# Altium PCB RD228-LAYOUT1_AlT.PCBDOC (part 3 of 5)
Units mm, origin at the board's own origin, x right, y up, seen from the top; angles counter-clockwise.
Board outline 130 x 73 mm, 4 copper layers (TOP, Mid-Layer 1, Mid-Layer 2, BOTTOM), stack 0.711 mm thick; 225 components, 171 nets, 818 pads, 538 vias.
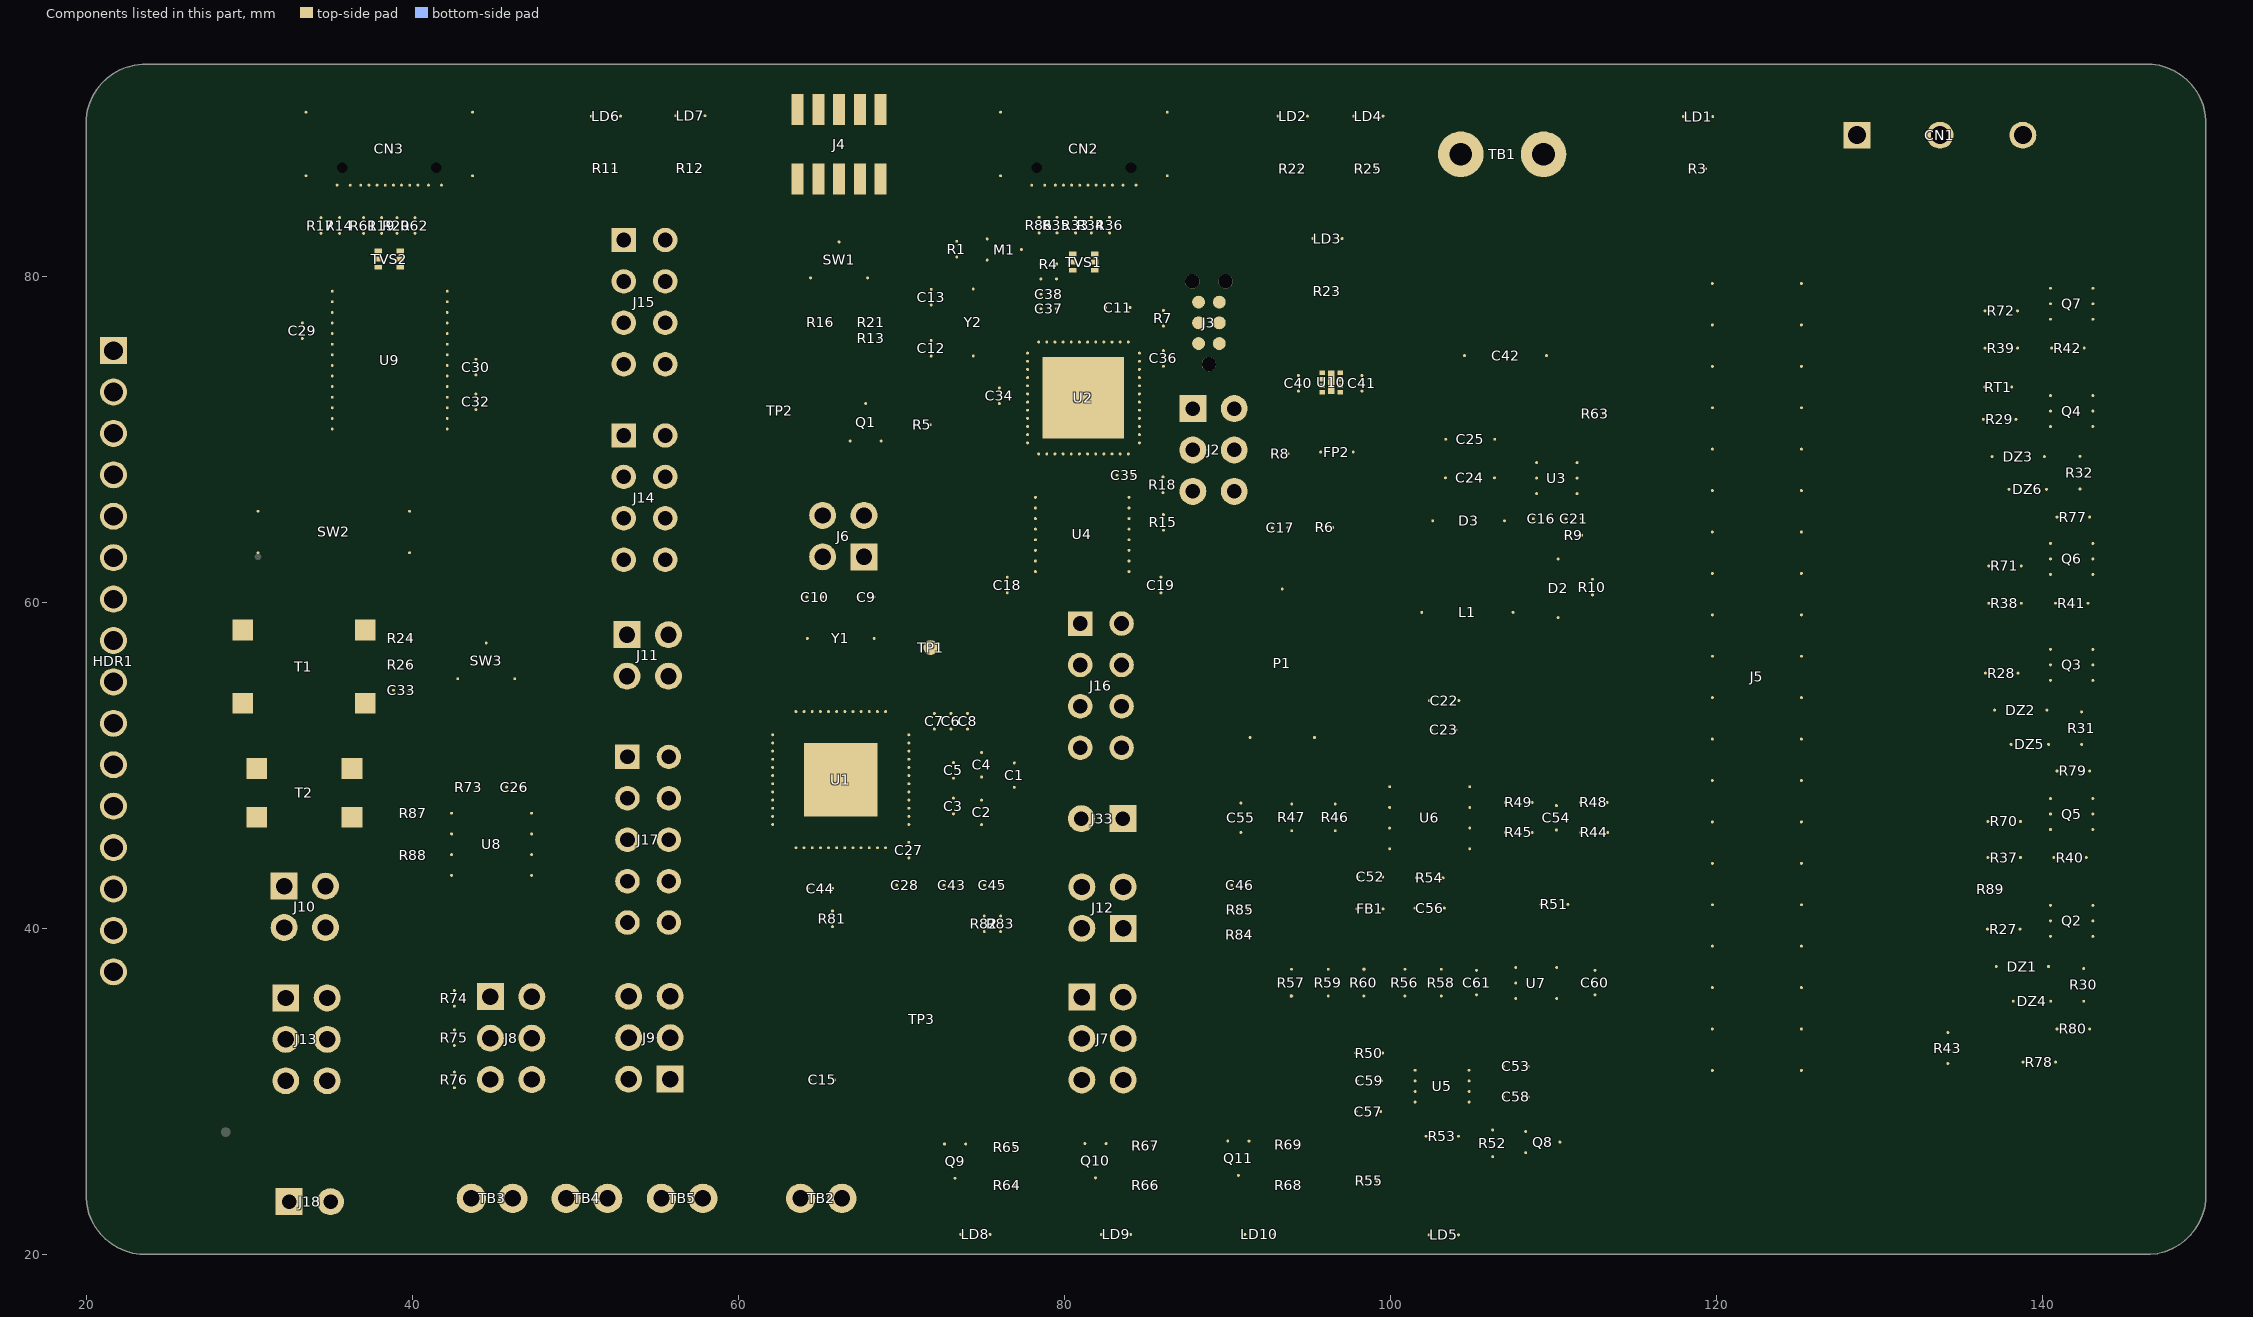
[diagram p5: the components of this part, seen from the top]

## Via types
v1: diameter 0.406, hole 0.203, TOP to BOTTOM, tented both sides, 533 vias
v2: diameter 6, hole 4.2, TOP to BOTTOM, 4 vias
v3: diameter 1.651, hole 1, TOP to BOTTOM, 1 vias

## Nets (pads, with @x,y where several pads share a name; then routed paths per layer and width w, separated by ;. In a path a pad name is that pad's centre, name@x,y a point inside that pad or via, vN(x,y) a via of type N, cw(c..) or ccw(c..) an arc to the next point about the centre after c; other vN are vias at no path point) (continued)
copper on no net:
  other v2: 24.24,27.502 145.739,27.502 24.24,85.502 145.74,85.502

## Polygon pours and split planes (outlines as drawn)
GND on TOP "TOP36" (solid, pour order 54): 31 vertices, not listed, extent 86.069,72.96 88.601,75.77
GND on TOP "TOP35" (solid, pour order 53): 49 vertices, not listed, extent 77.876,81.153 80.589,82.648
GND on TOP "TOP34" (solid, pour order 52): 45 vertices, not listed, extent 109.822,66.46 113.288,69.427
GND on TOP "TOP33" (solid, pour order 51): 25 vertices, not listed, extent 39.176,71.553 42.147,74.232
GND on TOP "TOP32" (solid, pour order 50): 398 vertices, not listed, extent 20.389,20.391 122.57,92.614
GND on TOP "TOP16" (solid, pour order 34): 117.334,30.702 117.057,30.979 117.057,36.389 117.619,36.951 121.223,36.951 121.223,30.702
GND on TOP "TOP11" (solid, pour order 29): 102.948,64.124 101.555,64.124 101.391,64.289 101.391,65.686 101.56,65.856 102.947,65.856
GND on TOP "TOP9" (solid, pour order 27): 103.748,69.128 102.356,69.128 102.191,69.292 102.191,70.69 102.36,70.86 103.748,70.86
GND on TOP "TOP10" (solid, pour order 28): 103.724,66.761 102.332,66.761 102.167,66.926 102.167,68.324 102.336,68.494 103.724,68.494
GND on TOP "TOP14" (solid, pour order 32): 102.527,74.499 102.349,74.677 102.349,75.541 102.501,75.693 103.848,75.693 103.848,74.499
GND on TOP "TOP5" (solid, pour order 23): 76.493,49.854 76.493,51.048 76.544,51.099 77.281,51.099 77.357,51.022 77.357,49.854
GND on TOP "TOP6" (solid, pour order 24): 74.487,50.489 74.487,51.683 74.538,51.734 75.274,51.734 75.35,51.657 75.35,50.489
GND on TOP "TOP7" (solid, pour order 25): 74.563,45.409 74.487,45.485 74.487,46.654 75.35,46.654 75.35,45.46 75.3,45.409
VCC-5V on TOP "TOP29" (solid, pour order 47): 103.428,51.367 103.29,51.505 103.29,54.947 102.973,55.264 101.462,55.264 101.081,55.645 101.081,62.859 101.284,63.062 103.824,63.062 103.976,62.91 103.976,57.195 105.627,55.544 105.627,51.505 105.49,51.367
GND on TOP "TOP13" (solid, pour order 31): 101.484,51.734 101.391,51.827 101.391,52.475 101.512,52.597 102.819,52.597 102.819,51.734
GND on TOP "TOP12" (solid, pour order 30): 101.385,53.359 101.208,53.537 101.208,54.401 101.36,54.553 102.706,54.553 102.706,53.359
VCC-3.3V on TOP "TOP31" (solid, pour order 49): 93.588,73.298 93.486,73.4 93.486,74.111 93.588,74.213 95.993,74.213 95.993,73.552 94.172,73.552 93.918,73.298
VCC-5V on TOP "TOP30" (solid, pour order 48): 94.707,68.599 94.529,68.777 94.529,69.641 94.681,69.793 96.028,69.793 96.028,68.599
NetC16_1 on TOP "TOP24" (solid, pour order 42): 106.084,55.696 105.576,56.204 105.576,65.499 106.441,66.364 107.405,66.364 108.015,66.974 109.64,66.974 109.844,66.77 109.844,66.224 109.234,65.615 109.234,56.153 108.777,55.696
VBAT on TOP "TOP18" (solid, pour order 36): 20 vertices, not listed, extent 104.916,66.796 121.325,90.519
VBAT on TOP "TOP17" (solid, pour order 35): 72.689,47.797 72.258,48.228 69.661,48.228 69.661,49.016 72.328,49.016 72.709,49.397 77.916,49.397 78.475,48.838 78.475,48.317 77.967,47.809 77.967,47.797
GND on TOP "TOP15" (solid, pour order 33): 96.483,72.231 96.178,72.536 96.178,72.968 96.204,72.993 97.906,72.993 98.007,73.095 98.49,73.095 98.49,72.509 98.195,72.231
GND on TOP "TOP8" (solid, pour order 26): 110.73,67.126 110.617,67.239 110.617,67.974 110.76,68.117 112.536,68.117 112.638,68.015 112.638,67.253 112.511,67.126
NetC41_2 on TOP "TOP1" (solid, pour order 19): 98.795,73.552 96.737,73.552 96.737,74.213 98.693,74.213 98.795,74.111
LS_SOURCE on TOP "TOP28" (solid, pour order 46): 132.094,33.801 132.094,35.274 132.272,35.452 135.904,35.452 136.26,35.097 136.26,33.801
LS_SOURCE on TOP "TOP27" (solid, pour order 45): 142.102,43.53 141.85,43.781 141.85,46.298 142.075,46.527 144.921,46.527 145.15,46.298 145.15,43.758 144.921,43.53
LS_SOURCE on TOP "TOP26" (solid, pour order 44): 142.102,59.125 141.85,59.377 141.85,61.894 142.1,62.148 144.896,62.148 145.15,61.894 145.15,59.354 144.921,59.125
LS_SOURCE on TOP "TOP25" (solid, pour order 43): 142.102,74.771 141.85,75.023 141.85,77.54 142.1,77.794 144.896,77.794 145.15,77.54 145.15,75 144.921,74.771
RSL_INT on TOP "TOP23" (solid, pour order 41): 125.363,28.442 123.61,30.194 123.61,36.848 123.764,37.002 126.506,37.002 126.76,36.748 126.76,31.49 126.735,31.439 127.166,31.007 131.611,31.007 132.119,31.515 132.145,31.49 136.26,31.49 136.26,29.763 134.939,28.442
VBAT_INT on TOP "TOP22" (solid, pour order 40): 139.968,40.052 139.765,40.255 139.765,42.795 140.095,43.126 143.575,43.126 143.88,42.821 143.88,40.281 143.651,40.052
VBAT_INT on TOP "TOP21" (solid, pour order 39): 139.968,55.75 139.765,55.953 139.765,58.493 140.095,58.823 143.575,58.823 143.88,58.519 143.88,55.979 143.651,55.75
VBAT_INT on TOP "TOP20" (solid, pour order 38): 139.968,71.317 139.765,71.52 139.765,74.06 140.095,74.39 143.575,74.39 143.88,74.086 143.88,71.546 143.651,71.317
VBAT_INT on TOP "TOP19" (solid, pour order 37): 122.401,73.873 122.036,74.238 122.036,79.851 122.34,80.156 126.608,80.156 126.785,79.978 126.785,74.06 126.598,73.873
PHASE_W on TOP "TOP4" (solid, pour order 22): 18 vertices, not listed, extent 138.241,69.615 148.071,79.953
PHASE_V on TOP "TOP3" (solid, pour order 21): 20 vertices, not listed, extent 138.241,53.969 148.071,64.307
PHASE_U on TOP "TOP2" (solid, pour order 20): 20 vertices, not listed, extent 138.241,38.323 148.071,48.661
GND on Mid-Layer 1 "MID143" (solid, pour order 18): 20 vertices, not listed, extent 77.55,58.217 100.714,60.897
GND on Mid-Layer 1 "MID142" (solid, pour order 17): 90.047,44.628 89.995,44.755 90.491,45.251 96.191,45.251 96.259,45.124 96.251,45.113 96.222,44.964 96.251,44.815 96.292,44.755 96.224,44.628
GND on Mid-Layer 1 "MID141" (solid, pour order 16): 32 vertices, not listed, extent 64.566,42.622 78.867,46.098
GND on Mid-Layer 1 "MID140" (solid, pour order 15): 90 vertices, not listed, extent 20.312,20.313 122.57,92.692
PHASE_W on Mid-Layer 1 "MID139" (solid, pour order 14): 146.47,72.46 146.216,72.714 146.216,76.321 137.403,85.135 137.403,89.503 137.758,89.859 139.689,89.859 140.12,89.427 140.12,86.137 148.452,77.806 148.452,72.714 148.198,72.46
PHASE_V on Mid-Layer 1 "MID138" (solid, pour order 13): 146.47,56.814 146.216,57.068 146.216,60.675 132.221,74.67 132.221,89.503 132.577,89.859 134.837,89.859 135.193,89.503 135.193,75.419 148.452,62.16 148.452,57.068 148.198,56.814
PHASE_U on Mid-Layer 1 "MID137" (solid, pour order 12): 146.47,41.168 146.216,41.422 146.216,45.029 127.192,64.054 127.192,89.554 127.497,89.859 129.757,89.859 130.113,89.503 130.113,64.853 148.452,46.514 148.452,41.422 148.198,41.168
GND on Mid-Layer 2 "MID247" (solid, pour order 11): 90 vertices, not listed, extent 20.312,20.313 122.57,92.692
PHASE_W on Mid-Layer 2 "MID246" (solid, pour order 10): 146.47,72.46 146.216,72.714 146.216,76.321 137.403,85.135 137.403,89.503 137.758,89.859 139.689,89.859 140.12,89.427 140.12,86.137 148.452,77.806 148.452,72.714 148.198,72.46
PHASE_V on Mid-Layer 2 "MID245" (solid, pour order 9): 146.47,56.814 146.216,57.068 146.216,60.675 132.221,74.67 132.221,89.503 132.577,89.859 134.837,89.859 135.193,89.503 135.193,75.419 148.452,62.16 148.452,57.068 148.198,56.814
PHASE_U on Mid-Layer 2 "MID244" (solid, pour order 8): 146.47,41.168 146.216,41.422 146.216,45.029 127.192,64.054 127.192,89.554 127.497,89.859 129.757,89.859 130.113,89.503 130.113,64.853 148.452,46.514 148.452,41.422 148.198,41.168
VCC-3.3V on BOTTOM "BOTTOM53" (solid, pour order 7): 74 vertices, not listed, extent 75.071,66.745 94.35,81.426
GND on BOTTOM "BOTTOM52" (solid, pour order 6): 50 vertices, not listed, extent 20.312,20.313 122.57,92.692
VBAT on BOTTOM "BOTTOM48" (solid, pour order 2): 77.484,47.822 77.23,48.076 77.23,48.965 77.484,49.219 78.221,49.219 78.475,48.965 78.475,48.076 78.221,47.822
LS_SOURCE on BOTTOM "BOTTOM51" (solid, pour order 5): 132.653,33.725 132.196,34.182 132.196,35.503 132.602,35.909 142.813,35.909 143.981,37.078 143.981,43.758 146.328,43.768 146.328,36.107 143.946,33.725
LS_SOURCE on BOTTOM "BOTTOM50" (solid, pour order 4): 144.21,43.529 144.007,43.733 144.007,77.261 144.159,77.413 146.166,77.413 146.328,77.25 146.328,43.768 146.089,43.529
VBAT_INT on BOTTOM "BOTTOM49" (solid, pour order 3): 140.247,41.726 139.765,42.209 139.765,73.247 138.088,74.924 122.417,74.924 122.137,75.203 122.137,79.623 122.366,79.851 138.977,79.851 143.803,75.025 143.804,42.234 143.295,41.726
no net on Top Overlay "TOPOVERLAY983" (solid, pour order 0): 216 vertices, not listed, extent 144.999,39.951 145.644,40.931
no net on Top Overlay "TOPOVERLAY982" (solid, pour order 0): 202 vertices, not listed, extent 143.956,39.876 144.909,40.945
no net on Top Overlay "TOPOVERLAY981" (solid, pour order 0): 312 vertices, not listed, extent 144.989,55.658 145.629,56.654
no net on Top Overlay "TOPOVERLAY980" (solid, pour order 0): 202 vertices, not listed, extent 143.93,55.599 144.883,56.667
no net on Top Overlay "TOPOVERLAY979" (solid, pour order 0): 94 vertices, not listed, extent 144.946,77.794 145.578,78.758
no net on Top Overlay "TOPOVERLAY978" (solid, pour order 0): 202 vertices, not listed, extent 143.88,77.719 144.832,78.788
no net on Top Overlay "TOPOVERLAY977" (solid, pour order 0): 202 vertices, not listed, extent 143.88,71.191 144.832,72.26
no net on Top Overlay "TOPOVERLAY976" (solid, pour order 0): 145.323,71.266 145.323,71.5 144.899,71.5 144.899,71.609 145.345,72.243 145.443,72.243 145.443,71.609 145.574,71.609 145.574,71.5 145.443,71.5 145.443,71.266
no net on Top Overlay "TOPOVERLAY975" (solid, pour order 0): 220 vertices, not listed, extent 144.933,62.131 145.578,63.128
no net on Top Overlay "TOPOVERLAY974" (solid, pour order 0): 202 vertices, not listed, extent 143.88,62.072 144.832,63.141
no net on Top Overlay "TOPOVERLAY973" (solid, pour order 0): 200 vertices, not listed, extent 144.938,46.524 145.586,47.504
no net on Top Overlay "TOPOVERLAY972" (solid, pour order 0): 202 vertices, not listed, extent 143.88,46.465 144.832,47.534
no net on Top Overlay "TOPOVERLAY971" (solid, pour order 0): 48 vertices, not listed, extent 145.511,59.481 145.87,60.461
no net on Top Overlay "TOPOVERLAY970" (solid, pour order 0): 119 vertices, not listed, extent 143.727,59.481 144.585,60.457
no net on Top Overlay "TOPOVERLAY969" (solid, pour order 0): 145.046,59.481 145.046,59.714 144.622,59.714 144.622,59.824 145.067,60.457 145.166,60.457 145.166,59.824 145.297,59.824 145.297,59.714 145.166,59.714 145.166,59.481
no net on Top Overlay "TOPOVERLAY968" (solid, pour order 0): 203 vertices, not listed, extent 144.634,33.277 145.277,34.273
no net on Top Overlay "TOPOVERLAY967" (solid, pour order 0): 151 vertices, not listed, extent 145.394,33.277 146.03,34.273
no net on Top Overlay "TOPOVERLAY966" (solid, pour order 0): 119 vertices, not listed, extent 143.702,33.293 144.56,34.27
no net on Top Overlay "TOPOVERLAY965" (solid, pour order 0): 312 vertices, not listed, extent 144.611,36.006 145.25,37.002
no net on Top Overlay "TOPOVERLAY964" (solid, pour order 0): 152 vertices, not listed, extent 145.368,36.006 146.004,37.002
no net on Top Overlay "TOPOVERLAY963" (solid, pour order 0): 119 vertices, not listed, extent 143.676,36.022 144.535,36.999
no net on Top Overlay "TOPOVERLAY962" (solid, pour order 0): 241 vertices, not listed, extent 145.267,49.152 145.909,50.148
no net on Top Overlay "TOPOVERLAY961" (solid, pour order 0): 119 vertices, not listed, extent 143.575,49.168 144.433,50.145
no net on Top Overlay "TOPOVERLAY960" (solid, pour order 0): 94 vertices, not listed, extent 144.517,49.168 145.148,50.132
no net on Top Overlay "TOPOVERLAY959" (solid, pour order 0): 151 vertices, not listed, extent 145.267,43.818 145.903,44.814
no net on Top Overlay "TOPOVERLAY958" (solid, pour order 0): 119 vertices, not listed, extent 143.575,43.834 144.433,44.811
no net on Top Overlay "TOPOVERLAY957" (solid, pour order 0): 144.893,43.834 144.893,44.068 144.469,44.068 144.469,44.177 144.915,44.811 145.013,44.811 145.013,44.177 145.145,44.177 145.145,44.068 145.013,44.068 145.013,43.834
no net on Top Overlay "TOPOVERLAY956" (solid, pour order 0): 94 vertices, not listed, extent 145.212,64.713 145.843,65.677
no net on Top Overlay "TOPOVERLAY955" (solid, pour order 0): 119 vertices, not listed, extent 143.511,64.713 144.37,65.689
no net on Top Overlay "TOPOVERLAY954" (solid, pour order 0): 94 vertices, not listed, extent 144.453,64.713 145.085,65.677
no net on Top Overlay "TOPOVERLAY953" (solid, pour order 0): 216 vertices, not listed, extent 145.175,75.127 145.82,76.107
no net on Top Overlay "TOPOVERLAY952" (solid, pour order 0): 119 vertices, not listed, extent 143.499,75.127 144.357,76.103
no net on Top Overlay "TOPOVERLAY951" (solid, pour order 0): 144.817,75.127 144.817,75.36 144.393,75.36 144.393,75.47 144.839,76.103 144.937,76.103 144.937,75.47 145.068,75.47 145.068,75.36 144.937,75.36 144.937,75.127
no net on Top Overlay "TOPOVERLAY950" (solid, pour order 0): 312 vertices, not listed, extent 144.408,51.754 145.047,52.75
no net on Top Overlay "TOPOVERLAY949" (solid, pour order 0): 119 vertices, not listed, extent 143.473,51.77 144.331,52.747
no net on Top Overlay "TOPOVERLAY948" (solid, pour order 0): 48 vertices, not listed, extent 145.257,51.77 145.616,52.75
no net on Top Overlay "TOPOVERLAY947" (solid, pour order 0): 312 vertices, not listed, extent 144.357,67.37 144.996,68.367
no net on Top Overlay "TOPOVERLAY946" (solid, pour order 0): 119 vertices, not listed, extent 143.422,67.386 144.281,68.363
no net on Top Overlay "TOPOVERLAY945" (solid, pour order 0): 216 vertices, not listed, extent 145.099,67.386 145.744,68.367
no net on Top Overlay "TOPOVERLAY944" (solid, pour order 0): 203 vertices, not listed, extent 140.338,29.797 140.981,30.794
no net on Top Overlay "TOPOVERLAY943" (solid, pour order 0): 119 vertices, not listed, extent 138.647,29.813 139.505,30.79
no net on Top Overlay "TOPOVERLAY942" (solid, pour order 0): 94 vertices, not listed, extent 139.589,29.813 140.221,30.777
no net on Top Overlay "TOPOVERLAY941" (solid, pour order 0): 138.093,82.163 137.707,83.79 138.044,83.79 138.289,82.671 138.585,83.79 138.976,83.79 139.262,82.653 139.511,83.79 139.843,83.79 139.447,82.163 139.098,82.163 138.774,83.379 138.452,82.163
no net on Top Overlay "TOPOVERLAY940" (solid, pour order 0): 28 vertices, not listed, extent 136.945,26.241 137.621,27.321
no net on Top Overlay "TOPOVERLAY939" (solid, pour order 0): 31 vertices, not listed, extent 137.699,26.239 138.391,27.318
no net on Top Overlay "TOPOVERLAY938" (solid, pour order 0): 137.017,34.998 137.017,35.232 136.593,35.232 136.593,35.341 137.039,35.975 137.137,35.975 137.137,35.341 137.269,35.341 137.269,35.232 137.137,35.232 137.137,34.998
no net on Top Overlay "TOPOVERLAY937" (solid, pour order 0): 100 vertices, not listed, extent 134.863,34.998 135.67,35.975
no net on Top Overlay "TOPOVERLAY936" (solid, pour order 0): 22 vertices, not listed, extent 135.769,34.998 136.542,35.975
no net on Top Overlay "TOPOVERLAY935" (solid, pour order 0): 200 vertices, not listed, extent 136.505,50.712 137.153,51.692
no net on Top Overlay "TOPOVERLAY934" (solid, pour order 0): 100 vertices, not listed, extent 134.736,50.728 135.543,51.704
no net on Top Overlay "TOPOVERLAY933" (solid, pour order 0): 22 vertices, not listed, extent 135.642,50.728 136.415,51.704
no net on Top Overlay "TOPOVERLAY932" (solid, pour order 0): 220 vertices, not listed, extent 136.272,66.323 136.917,67.32
no net on Top Overlay "TOPOVERLAY931" (solid, pour order 0): 100 vertices, not listed, extent 134.507,66.34 135.315,67.316
no net on Top Overlay "TOPOVERLAY930" (solid, pour order 0): 22 vertices, not listed, extent 135.414,66.34 136.186,67.316
no net on Top Overlay "TOPOVERLAY929" (solid, pour order 0): 48 vertices, not listed, extent 135.683,37.106 136.043,38.087
no net on Top Overlay "TOPOVERLAY928" (solid, pour order 0): 100 vertices, not listed, extent 133.821,37.106 134.629,38.083
no net on Top Overlay "TOPOVERLAY927" (solid, pour order 0): 22 vertices, not listed, extent 134.728,37.106 135.501,38.083
no net on Top Overlay "TOPOVERLAY926" (solid, pour order 0): 48 vertices, not listed, extent 135.326,61.665 135.685,62.645
no net on Top Overlay "TOPOVERLAY925" (solid, pour order 0): 119 vertices, not listed, extent 133.542,61.665 134.4,62.641
no net on Top Overlay "TOPOVERLAY924" (solid, pour order 0): 94 vertices, not listed, extent 134.484,61.665 135.115,62.629
no net on Top Overlay "TOPOVERLAY923" (solid, pour order 0): 216 vertices, not listed, extent 135.296,52.804 135.941,53.784
no net on Top Overlay "TOPOVERLAY922" (solid, pour order 0): 100 vertices, not listed, extent 133.542,52.804 134.35,53.78
no net on Top Overlay "TOPOVERLAY921" (solid, pour order 0): 22 vertices, not listed, extent 134.449,52.804 135.221,53.78
no net on Top Overlay "TOPOVERLAY920" (solid, pour order 0): 203 vertices, not listed, extent 135.131,59.414 135.774,60.41
no net on Top Overlay "TOPOVERLAY919" (solid, pour order 0): 312 vertices, not listed, extent 134.375,59.414 135.014,60.41
no net on Top Overlay "TOPOVERLAY918" (solid, pour order 0): 119 vertices, not listed, extent 133.44,59.43 134.298,60.406
no net on Top Overlay "TOPOVERLAY917" (solid, pour order 0): 48 vertices, not listed, extent 135.249,72.663 135.608,73.643
no net on Top Overlay "TOPOVERLAY916" (solid, pour order 0): 119 vertices, not listed, extent 133.389,72.663 134.248,73.64
no net on Top Overlay "TOPOVERLAY915" (solid, pour order 0): 134.62,72.663 134.62,73.524 134.298,73.524 134.298,73.64 135.073,73.64 135.073,73.524 134.75,73.524 134.75,72.663
no net on Top Overlay "TOPOVERLAY914" (solid, pour order 0): 94 vertices, not listed, extent 134.332,45.968 134.963,46.932
no net on Top Overlay "TOPOVERLAY913" (solid, pour order 0): 151 vertices, not listed, extent 135.081,45.952 135.717,46.948
no net on Top Overlay "TOPOVERLAY912" (solid, pour order 0): 119 vertices, not listed, extent 133.389,45.968 134.248,46.944
no net on Top Overlay "TOPOVERLAY911" (solid, pour order 0): 312 vertices, not listed, extent 134.324,43.793 134.963,44.789
no net on Top Overlay "TOPOVERLAY910" (solid, pour order 0): 119 vertices, not listed, extent 133.389,43.809 134.248,44.785
no net on Top Overlay "TOPOVERLAY909" (solid, pour order 0): 94 vertices, not listed, extent 135.09,43.809 135.721,44.773
no net on Top Overlay "TOPOVERLAY908" (solid, pour order 0): 203 vertices, not listed, extent 134.322,41.862 134.965,42.859
no net on Top Overlay "TOPOVERLAY907" (solid, pour order 0): 119 vertices, not listed, extent 133.389,41.878 134.248,42.855
no net on Top Overlay "TOPOVERLAY906" (solid, pour order 0): 241 vertices, not listed, extent 135.081,41.862 135.723,42.859
no net on Top Overlay "TOPOVERLAY905" (solid, pour order 0): 312 vertices, not listed, extent 135.135,68.456 135.774,69.452
no net on Top Overlay "TOPOVERLAY904" (solid, pour order 0): 100 vertices, not listed, extent 133.364,68.472 134.172,69.449
no net on Top Overlay "TOPOVERLAY903" (solid, pour order 0): 22 vertices, not listed, extent 134.271,68.472 135.043,69.449
no net on Top Overlay "TOPOVERLAY902" (solid, pour order 0): 94 vertices, not listed, extent 135.064,39.418 135.696,40.382
no net on Top Overlay "TOPOVERLAY901" (solid, pour order 0): 119 vertices, not listed, extent 133.364,39.418 134.222,40.394
no net on Top Overlay "TOPOVERLAY900" (solid, pour order 0): 216 vertices, not listed, extent 134.282,39.418 134.927,40.398
no net on Top Overlay "TOPOVERLAY899" (solid, pour order 0): 203 vertices, not listed, extent 134.979,55.124 135.622,56.121
no net on Top Overlay "TOPOVERLAY898" (solid, pour order 0): 119 vertices, not listed, extent 133.288,55.14 134.146,56.117
no net on Top Overlay "TOPOVERLAY897" (solid, pour order 0): 216 vertices, not listed, extent 134.206,55.14 134.851,56.121
no net on Top Overlay "TOPOVERLAY896" (solid, pour order 0): 312 vertices, not listed, extent 134.121,75.187 134.76,76.183
no net on Top Overlay "TOPOVERLAY895" (solid, pour order 0): 119 vertices, not listed, extent 133.186,75.203 134.044,76.18
no net on Top Overlay "TOPOVERLAY894" (solid, pour order 0): 241 vertices, not listed, extent 134.878,75.187 135.52,76.183
no net on Top Overlay "TOPOVERLAY893" (solid, pour order 0): 133.715,82.239 133.135,83.866 133.491,83.866 133.902,82.661 134.302,83.866 134.652,83.866 134.069,82.239
no net on Top Overlay "TOPOVERLAY892" (solid, pour order 0): 216 vertices, not listed, extent 134.761,77.362 135.406,78.342
no net on Top Overlay "TOPOVERLAY891" (solid, pour order 0): 119 vertices, not listed, extent 133.085,77.362 133.943,78.339
no net on Top Overlay "TOPOVERLAY890" (solid, pour order 0): 94 vertices, not listed, extent 134.027,77.362 134.658,78.326
no net on Top Overlay "TOPOVERLAY889" (solid, pour order 0): 241 vertices, not listed, extent 134.776,70.742 135.418,71.738
no net on Top Overlay "TOPOVERLAY888" (solid, pour order 0): 119 vertices, not listed, extent 133.085,70.758 133.943,71.735
no net on Top Overlay "TOPOVERLAY887" (solid, pour order 0): 216 vertices, not listed, extent 134.003,70.758 134.648,71.738
no net on Top Overlay "TOPOVERLAY886" (solid, pour order 0): 312 vertices, not listed, extent 134.752,29.848 135.391,30.844
no net on Top Overlay "TOPOVERLAY885" (solid, pour order 0): 119 vertices, not listed, extent 133.059,29.864 133.917,30.841
no net on Top Overlay "TOPOVERLAY884" (solid, pour order 0): 134.378,29.864 134.378,30.098 133.954,30.098 133.954,30.207 134.399,30.841 134.498,30.841 134.498,30.207 134.629,30.207 134.629,30.098 134.498,30.098 134.498,29.864
no net on Top Overlay "TOPOVERLAY883" (solid, pour order 0): 128.411,76.516 128.411,76.749 127.987,76.749 127.987,76.859 128.432,77.492 128.531,77.492 128.531,76.859 128.662,76.859 128.662,76.749 128.531,76.749 128.531,76.516
no net on Top Overlay "TOPOVERLAY882" (solid, pour order 0): 220 vertices, not listed, extent 127.987,73.96 128.632,74.956
no net on Top Overlay "TOPOVERLAY881" (solid, pour order 0): 203 vertices, not listed, extent 127.987,71.42 128.63,72.416
no net on Top Overlay "TOPOVERLAY880" (solid, pour order 0): 48 vertices, not listed, extent 127.987,68.896 128.346,69.876
no net on Top Overlay "TOPOVERLAY879" (solid, pour order 0): 151 vertices, not listed, extent 128.653,68.88 129.289,69.876
no net on Top Overlay "TOPOVERLAY878" (solid, pour order 0): 216 vertices, not listed, extent 128.637,66.356 129.282,67.336
no net on Top Overlay "TOPOVERLAY877" (solid, pour order 0): 48 vertices, not listed, extent 127.987,66.356 128.346,67.336
no net on Top Overlay "TOPOVERLAY876" (solid, pour order 0): 129.037,63.816 129.037,64.049 128.613,64.049 128.613,64.159 129.059,64.792 129.157,64.792 129.157,64.159 129.289,64.159 129.289,64.049 129.157,64.049 129.157,63.816
no net on Top Overlay "TOPOVERLAY875" (solid, pour order 0): 48 vertices, not listed, extent 127.987,63.816 128.346,64.796
no net on Top Overlay "TOPOVERLAY874" (solid, pour order 0): 220 vertices, not listed, extent 128.648,61.26 129.293,62.256
no net on Top Overlay "TOPOVERLAY873" (solid, pour order 0): 48 vertices, not listed, extent 127.987,61.276 128.346,62.256
no net on Top Overlay "TOPOVERLAY872" (solid, pour order 0): 203 vertices, not listed, extent 128.652,58.72 129.295,59.716
no net on Top Overlay "TOPOVERLAY871" (solid, pour order 0): 48 vertices, not listed, extent 127.987,58.736 128.346,59.716
no net on Top Overlay "TOPOVERLAY870" (solid, pour order 0): 216 vertices, not listed, extent 127.988,56.196 128.633,57.176
no net on Top Overlay "TOPOVERLAY869" (solid, pour order 0): 151 vertices, not listed, extent 128.761,56.18 129.397,57.176
no net on Top Overlay "TOPOVERLAY868" (solid, pour order 0): 216 vertices, not listed, extent 128.746,53.656 129.391,54.636
no net on Top Overlay "TOPOVERLAY867" (solid, pour order 0): 216 vertices, not listed, extent 127.988,53.656 128.633,54.636
no net on Top Overlay "TOPOVERLAY866" (solid, pour order 0): 129.146,51.116 129.146,51.349 128.722,51.349 128.722,51.459 129.168,52.092 129.266,52.092 129.266,51.459 129.397,51.459 129.397,51.349 129.266,51.349 129.266,51.116
no net on Top Overlay "TOPOVERLAY865" (solid, pour order 0): 216 vertices, not listed, extent 127.988,51.116 128.633,52.096
no net on Top Overlay "TOPOVERLAY864" (solid, pour order 0): 220 vertices, not listed, extent 128.756,48.56 129.401,49.556
no net on Top Overlay "TOPOVERLAY863" (solid, pour order 0): 216 vertices, not listed, extent 127.988,48.576 128.633,49.556
no net on Top Overlay "TOPOVERLAY862" (solid, pour order 0): 203 vertices, not listed, extent 128.76,46.02 129.403,47.016
no net on Top Overlay "TOPOVERLAY861" (solid, pour order 0): 216 vertices, not listed, extent 127.988,46.036 128.633,47.016
no net on Top Overlay "TOPOVERLAY860" (solid, pour order 0): 312 vertices, not listed, extent 127.987,43.48 128.626,44.476
no net on Top Overlay "TOPOVERLAY859" (solid, pour order 0): 151 vertices, not listed, extent 128.744,43.48 129.38,44.476
no net on Top Overlay "TOPOVERLAY858" (solid, pour order 0): 312 vertices, not listed, extent 127.987,40.94 128.626,41.936
no net on Top Overlay "TOPOVERLAY857" (solid, pour order 0): 216 vertices, not listed, extent 128.729,40.956 129.374,41.936
no net on Top Overlay "TOPOVERLAY856" (solid, pour order 0): 312 vertices, not listed, extent 127.987,38.4 128.626,39.396
no net on Top Overlay "TOPOVERLAY855" (solid, pour order 0): 129.129,38.416 129.129,38.649 128.705,38.649 128.705,38.759 129.151,39.392 129.249,39.392 129.249,38.759 129.38,38.759 129.38,38.649 129.249,38.649 129.249,38.416
no net on Top Overlay "TOPOVERLAY854" (solid, pour order 0): 220 vertices, not listed, extent 128.739,35.86 129.384,36.856
no net on Top Overlay "TOPOVERLAY853" (solid, pour order 0): 312 vertices, not listed, extent 127.987,35.86 128.626,36.856
no net on Top Overlay "TOPOVERLAY852" (solid, pour order 0): 216 vertices, not listed, extent 127.986,79.056 128.631,80.036
no net on Top Overlay "TOPOVERLAY851" (solid, pour order 0): 312 vertices, not listed, extent 127.985,33.32 128.624,34.316
no net on Top Overlay "TOPOVERLAY850" (solid, pour order 0): 203 vertices, not listed, extent 128.742,33.32 129.385,34.316
no net on Top Overlay "TOPOVERLAY849" (solid, pour order 0): 151 vertices, not listed, extent 128.783,30.78 129.419,31.776
no net on Top Overlay "TOPOVERLAY848" (solid, pour order 0): 128.409,30.796 128.409,31.029 127.985,31.029 127.985,31.139 128.431,31.772 128.529,31.772 128.529,31.139 128.661,31.139 128.661,31.029 128.529,31.029 128.529,30.796
no net on Top Overlay "TOPOVERLAY847" (solid, pour order 0): 156 vertices, not listed, extent 127.979,82.252 129.276,83.907
no net on Top Overlay "TOPOVERLAY846" (solid, pour order 0): 58 vertices, not listed, extent 127.319,23.71 128.778,27.112
no net on Top Overlay "TOPOVERLAY845" (solid, pour order 0): 211 vertices, not listed, extent 132.005,23.713 134.061,27.431
no net on Top Overlay "TOPOVERLAY844" (solid, pour order 0): 71 vertices, not listed, extent 134.558,23.816 136.682,27.328
no net on Top Overlay "TOPOVERLAY843" (solid, pour order 0): 28 vertices, not listed, extent 129.456,23.807 131.668,27.318
no net on Top Overlay "TOPOVERLAY842" (solid, pour order 0): 55 vertices, not listed, extent 125.411,23.648 126.982,26.297
no net on Top Overlay "TOPOVERLAY841" (solid, pour order 0): 274 vertices, not listed, extent 123.229,88.09 124.092,89.1
no net on Top Overlay "TOPOVERLAY840" (solid, pour order 0): 124.251,88.106 124.251,89.083 124.383,89.083 124.896,88.316 124.896,89.083 125.02,89.083 125.02,88.106 124.887,88.106 124.374,88.872 124.374,88.106
no net on Top Overlay "TOPOVERLAY839" (solid, pour order 0): 48 vertices, not listed, extent 125.28,88.106 125.639,89.087
no net on Top Overlay "TOPOVERLAY838" (solid, pour order 0): 110 vertices, not listed, extent 121.785,81.689 122.322,82.682
no net on Top Overlay "TOPOVERLAY837" (solid, pour order 0): 200 vertices, not listed, extent 122.484,81.689 123.131,82.67
no net on Top Overlay "TOPOVERLAY836" (solid, pour order 0): 270 vertices, not listed, extent 118.099,23.466 120.139,27.168
no net on Top Overlay "TOPOVERLAY835" (solid, pour order 0): 139 vertices, not listed, extent 120.392,23.632 122.807,26.297
no net on Top Overlay "TOPOVERLAY834" (solid, pour order 0): 169 vertices, not listed, extent 123.066,23.541 125.128,26.272
no net on Top Overlay "TOPOVERLAY833" (solid, pour order 0): 312 vertices, not listed, extent 118.982,85.068 119.621,86.064
no net on Top Overlay "TOPOVERLAY832" (solid, pour order 0): 119 vertices, not listed, extent 118.048,85.084 118.906,86.06
no net on Top Overlay "TOPOVERLAY831" (solid, pour order 0): 96 vertices, not listed, extent 118.158,87.624 119.414,88.6
no net on Top Overlay "TOPOVERLAY830" (solid, pour order 0): 75 vertices, not listed, extent 117.337,87.624 118.082,88.6
no net on Top Overlay "TOPOVERLAY829" (solid, pour order 0): 119 vertices, not listed, extent 119.537,87.624 120.395,88.6
no net on Top Overlay "TOPOVERLAY828" (solid, pour order 0): 48 vertices, not listed, extent 116.594,79.056 116.953,80.036
no net on Top Overlay "TOPOVERLAY827" (solid, pour order 0): 94 vertices, not listed, extent 116.322,71.436 116.953,72.4
no net on Top Overlay "TOPOVERLAY826" (solid, pour order 0): 312 vertices, not listed, extent 116.315,76.5 116.954,77.496
no net on Top Overlay "TOPOVERLAY825" (solid, pour order 0): 241 vertices, not listed, extent 116.312,68.88 116.954,69.876
no net on Top Overlay "TOPOVERLAY824" (solid, pour order 0): 200 vertices, not listed, extent 116.306,73.96 116.954,74.94
no net on Top Overlay "TOPOVERLAY823" (solid, pour order 0): 48 vertices, not listed, extent 116.594,66.356 116.953,67.336
no net on Top Overlay "TOPOVERLAY822" (solid, pour order 0): 48 vertices, not listed, extent 115.835,66.356 116.194,67.336
no net on Top Overlay "TOPOVERLAY821" (solid, pour order 0): 312 vertices, not listed, extent 115.745,40.94 116.384,41.936
no net on Top Overlay "TOPOVERLAY820" (solid, pour order 0): 48 vertices, not listed, extent 116.595,40.956 116.954,41.936
no net on Top Overlay "TOPOVERLAY819" (solid, pour order 0): 48 vertices, not listed, extent 116.592,53.656 116.951,54.636
no net on Top Overlay "TOPOVERLAY818" (solid, pour order 0): 216 vertices, not listed, extent 115.726,53.656 116.371,54.636
no net on Top Overlay "TOPOVERLAY817" (solid, pour order 0): 312 vertices, not listed, extent 116.313,63.8 116.952,64.796
no net on Top Overlay "TOPOVERLAY816" (solid, pour order 0): 48 vertices, not listed, extent 115.646,63.816 116.006,64.796
no net on Top Overlay "TOPOVERLAY815" (solid, pour order 0): 93 vertices, not listed, extent 116.321,58.736 116.952,59.7
no net on Top Overlay "TOPOVERLAY814" (solid, pour order 0): 48 vertices, not listed, extent 115.646,58.736 116.006,59.716
no net on Top Overlay "TOPOVERLAY813" (solid, pour order 0): 241 vertices, not listed, extent 116.311,56.18 116.953,57.176
no net on Top Overlay "TOPOVERLAY812" (solid, pour order 0): 48 vertices, not listed, extent 115.645,56.196 116.004,57.176
no net on Top Overlay "TOPOVERLAY811" (solid, pour order 0): 200 vertices, not listed, extent 116.305,61.26 116.953,62.24
no net on Top Overlay "TOPOVERLAY810" (solid, pour order 0): 48 vertices, not listed, extent 115.639,61.276 115.999,62.256
no net on Top Overlay "TOPOVERLAY809" (solid, pour order 0): 312 vertices, not listed, extent 116.314,38.4 116.954,39.396
no net on Top Overlay "TOPOVERLAY808" (solid, pour order 0): 312 vertices, not listed, extent 115.556,38.4 116.195,39.396
no net on Top Overlay "TOPOVERLAY807" (solid, pour order 0): 312 vertices, not listed, extent 115.556,33.32 116.195,34.316
no net on Top Overlay "TOPOVERLAY806" (solid, pour order 0): 93 vertices, not listed, extent 116.322,33.336 116.954,34.3
no net on Top Overlay "TOPOVERLAY805" (solid, pour order 0): 312 vertices, not listed, extent 115.555,30.78 116.194,31.776
no net on Top Overlay "TOPOVERLAY804" (solid, pour order 0): 241 vertices, not listed, extent 116.312,30.78 116.954,31.776
no net on Top Overlay "TOPOVERLAY803" (solid, pour order 0): 312 vertices, not listed, extent 115.549,35.86 116.188,36.856
no net on Top Overlay "TOPOVERLAY802" (solid, pour order 0): 200 vertices, not listed, extent 116.306,35.86 116.954,36.84
no net on Top Overlay "TOPOVERLAY801" (solid, pour order 0): 312 vertices, not listed, extent 116.312,51.1 116.951,52.096
no net on Top Overlay "TOPOVERLAY800" (solid, pour order 0): 216 vertices, not listed, extent 115.537,51.116 116.182,52.096
no net on Top Overlay "TOPOVERLAY799" (solid, pour order 0): 93 vertices, not listed, extent 116.319,46.036 116.951,47
no net on Top Overlay "TOPOVERLAY798" (solid, pour order 0): 216 vertices, not listed, extent 115.537,46.036 116.182,47.016
no net on Top Overlay "TOPOVERLAY797" (solid, pour order 0): 241 vertices, not listed, extent 116.309,43.48 116.951,44.476
no net on Top Overlay "TOPOVERLAY796" (solid, pour order 0): 216 vertices, not listed, extent 115.536,43.496 116.181,44.476
no net on Top Overlay "TOPOVERLAY795" (solid, pour order 0): 200 vertices, not listed, extent 116.304,48.56 116.952,49.54
no net on Top Overlay "TOPOVERLAY794" (solid, pour order 0): 216 vertices, not listed, extent 115.53,48.576 116.175,49.556
no net on Top Overlay "TOPOVERLAY793" (solid, pour order 0): 48 vertices, not listed, extent 114.904,86.811 115.263,87.791
no net on Top Overlay "TOPOVERLAY792" (solid, pour order 0): 113.366,86.811 113.366,87.672 113.044,87.672 113.044,87.787 113.818,87.787 113.818,87.672 113.496,87.672 113.496,86.811
no net on Top Overlay "TOPOVERLAY791" (solid, pour order 0): 117 vertices, not listed, extent 113.946,86.811 114.683,87.787
no net on Top Overlay "TOPOVERLAY790" (solid, pour order 0): 204 vertices, not listed, extent 115.745,81.713 116.387,82.711
no net on Top Overlay "TOPOVERLAY789" (solid, pour order 0): 229 vertices, not listed, extent 118.786,81.715 119.637,82.725
no net on Top Overlay "TOPOVERLAY788" (solid, pour order 0): 203 vertices, not listed, extent 113.019,81.715 113.67,82.711
no net on Top Overlay "TOPOVERLAY787" (solid, pour order 0): 114.174,81.991 114.174,82.178 114.542,82.178 114.542,81.991
no net on Top Overlay "TOPOVERLAY786" (solid, pour order 0): 98 vertices, not listed, extent 117.835,81.731 118.654,82.707
no net on Top Overlay "TOPOVERLAY785" (solid, pour order 0): 47 vertices, not listed, extent 115.039,81.731 115.468,82.711
no net on Top Overlay "TOPOVERLAY784" (solid, pour order 0): 116.795,81.731 116.448,82.707 116.661,82.707 116.908,81.984 117.148,82.707 117.357,82.707 117.008,81.731
no net on Top Overlay "TOPOVERLAY783" (solid, pour order 0): 220 vertices, not listed, extent 112.322,72.139 112.967,73.135
no net on Top Overlay "TOPOVERLAY782" (solid, pour order 0): 312 vertices, not listed, extent 113.086,72.139 113.725,73.135
no net on Top Overlay "TOPOVERLAY781" (solid, pour order 0): 119 vertices, not listed, extent 111.393,72.155 112.251,73.132
no net on Top Overlay "TOPOVERLAY780" (solid, pour order 0): 220 vertices, not listed, extent 112.362,38.205 113.007,39.201
no net on Top Overlay "TOPOVERLAY779" (solid, pour order 0): 274 vertices, not listed, extent 111.393,38.205 112.256,39.214
no net on Top Overlay "TOPOVERLAY778" (solid, pour order 0): 151 vertices, not listed, extent 113.125,38.205 113.761,39.201
no net on Top Overlay "TOPOVERLAY777" (solid, pour order 0): 119 vertices, not listed, extent 111.342,44.063 112.2,45.039
no net on Top Overlay "TOPOVERLAY776" (solid, pour order 0): 112.661,44.063 112.661,44.296 112.237,44.296 112.237,44.406 112.682,45.039 112.781,45.039 112.781,44.406 112.912,44.406 112.912,44.296 112.781,44.296 112.781,44.063
no net on Top Overlay "TOPOVERLAY775" (solid, pour order 0): 113.419,44.063 113.419,44.296 112.995,44.296 112.995,44.406 113.441,45.039 113.539,45.039 113.539,44.406 113.67,44.406 113.67,44.296 113.539,44.296 113.539,44.063
no net on Top Overlay "TOPOVERLAY774" (solid, pour order 0): 203 vertices, not listed, extent 112.982,48.542 113.625,49.539
no net on Top Overlay "TOPOVERLAY773" (solid, pour order 0): 119 vertices, not listed, extent 111.291,48.559 112.15,49.535
no net on Top Overlay "TOPOVERLAY772" (solid, pour order 0): 112.61,48.559 112.61,48.792 112.186,48.792 112.186,48.902 112.632,49.535 112.73,49.535 112.73,48.902 112.861,48.902 112.861,48.792 112.73,48.792 112.73,48.559
no net on Top Overlay "TOPOVERLAY771" (solid, pour order 0): 202 vertices, not listed, extent 111.19,26.335 112.142,27.403
no net on Top Overlay "TOPOVERLAY770" (solid, pour order 0): 203 vertices, not listed, extent 112.247,26.394 112.89,27.39
no net on Top Overlay "TOPOVERLAY769" (solid, pour order 0): 216 vertices, not listed, extent 110.485,57.195 111.13,58.175
no net on Top Overlay "TOPOVERLAY768" (solid, pour order 0): 100 vertices, not listed, extent 109.564,57.195 110.372,58.171
no net on Top Overlay "TOPOVERLAY767" (solid, pour order 0): 312 vertices, not listed, extent 110.422,69.497 111.062,70.494
no net on Top Overlay "TOPOVERLAY766" (solid, pour order 0): 148 vertices, not listed, extent 109.488,69.497 110.256,70.49
no net on Top Overlay "TOPOVERLAY765" (solid, pour order 0): 274 vertices, not listed, extent 109.285,31.042 110.148,32.052
no net on Top Overlay "TOPOVERLAY764" (solid, pour order 0): 312 vertices, not listed, extent 111.017,31.042 111.657,32.038
no net on Top Overlay "TOPOVERLAY763" (solid, pour order 0): 200 vertices, not listed, extent 110.258,31.042 110.906,32.022
no net on Top Overlay "TOPOVERLAY762" (solid, pour order 0): 274 vertices, not listed, extent 109.234,29.162 110.097,30.172
no net on Top Overlay "TOPOVERLAY761" (solid, pour order 0): 203 vertices, not listed, extent 110.965,29.162 111.608,30.159
no net on Top Overlay "TOPOVERLAY760" (solid, pour order 0): 200 vertices, not listed, extent 110.208,29.162 110.855,30.142
no net on Top Overlay "TOPOVERLAY759" (solid, pour order 0): 200 vertices, not listed, extent 109.819,42.37 110.467,43.35
no net on Top Overlay "TOPOVERLAY758" (solid, pour order 0): 119 vertices, not listed, extent 108.886,42.386 109.744,43.363
no net on Top Overlay "TOPOVERLAY757" (solid, pour order 0): 48 vertices, not listed, extent 110.67,42.386 111.029,43.367
no net on Top Overlay "TOPOVERLAY756" (solid, pour order 0): 148 vertices, not listed, extent 108.218,38.255 108.986,39.248
no net on Top Overlay "TOPOVERLAY755" (solid, pour order 0): 94 vertices, not listed, extent 109.16,38.272 109.792,39.236
no net on Top Overlay "TOPOVERLAY754" (solid, pour order 0): 119 vertices, not listed, extent 106.694,48.559 107.552,49.535
no net on Top Overlay "TOPOVERLAY753" (solid, pour order 0): 108.012,48.559 108.012,48.792 107.588,48.792 107.588,48.902 108.034,49.535 108.132,49.535 108.132,48.902 108.264,48.902 108.264,48.792 108.132,48.792 108.132,48.559
no net on Top Overlay "TOPOVERLAY752" (solid, pour order 0): 241 vertices, not listed, extent 108.386,48.542 109.028,49.539
no net on Top Overlay "TOPOVERLAY751" (solid, pour order 0): 200 vertices, not listed, extent 108.386,44.072 109.033,45.052
no net on Top Overlay "TOPOVERLAY750" (solid, pour order 0): 119 vertices, not listed, extent 106.694,44.088 107.552,45.065
no net on Top Overlay "TOPOVERLAY749" (solid, pour order 0): 108.012,44.088 108.012,44.322 107.588,44.322 107.588,44.431 108.034,45.065 108.132,45.065 108.132,44.431 108.264,44.431 108.264,44.322 108.132,44.322 108.132,44.088
no net on Top Overlay "TOPOVERLAY748" (solid, pour order 0): 274 vertices, not listed, extent 105.17,53.419 106.033,54.429
no net on Top Overlay "TOPOVERLAY747" (solid, pour order 0): 216 vertices, not listed, extent 106.886,53.435 107.531,54.416
no net on Top Overlay "TOPOVERLAY746" (solid, pour order 0): 216 vertices, not listed, extent 106.128,53.435 106.773,54.416
no net on Top Overlay "TOPOVERLAY745" (solid, pour order 0): 200 vertices, not listed, extent 106.078,24.311 106.726,25.291
no net on Top Overlay "TOPOVERLAY744" (solid, pour order 0): 119 vertices, not listed, extent 105.145,24.327 106.003,25.303
no net on Top Overlay "TOPOVERLAY743" (solid, pour order 0): 216 vertices, not listed, extent 106.821,24.327 107.466,25.307
no net on Top Overlay "TOPOVERLAY742" (solid, pour order 0): 274 vertices, not listed, extent 104.84,51.641 105.703,52.651
no net on Top Overlay "TOPOVERLAY741" (solid, pour order 0): 312 vertices, not listed, extent 106.572,51.641 107.212,52.638
no net on Top Overlay "TOPOVERLAY740" (solid, pour order 0): 216 vertices, not listed, extent 105.798,51.657 106.443,52.638
no net on Top Overlay "TOPOVERLAY739" (solid, pour order 0): 220 vertices, not listed, extent 105.983,40.745 106.627,41.741
no net on Top Overlay "TOPOVERLAY738" (solid, pour order 0): 274 vertices, not listed, extent 104.256,40.745 105.119,41.754
no net on Top Overlay "TOPOVERLAY737" (solid, pour order 0): 200 vertices, not listed, extent 105.229,40.745 105.877,41.725
no net on Top Overlay "TOPOVERLAY736" (solid, pour order 0): 220 vertices, not listed, extent 105.174,38.179 105.818,39.176
no net on Top Overlay "TOPOVERLAY735" (solid, pour order 0): 274 vertices, not listed, extent 104.205,38.179 105.068,39.189
no net on Top Overlay "TOPOVERLAY734" (solid, pour order 0): 48 vertices, not listed, extent 106.029,38.195 106.388,39.176
no net on Top Overlay "TOPOVERLAY733" (solid, pour order 0): 200 vertices, not listed, extent 104.91,42.624 105.557,43.604
no net on Top Overlay "TOPOVERLAY732" (solid, pour order 0): 119 vertices, not listed, extent 103.976,42.64 104.834,43.617
no net on Top Overlay "TOPOVERLAY731" (solid, pour order 0): 106.053,42.64 106.053,42.874 105.629,42.874 105.629,42.983 106.075,43.617 106.173,43.617 106.173,42.983 106.304,42.983 106.304,42.874 106.173,42.874 106.173,42.64
no net on Top Overlay "TOPOVERLAY730" (solid, pour order 0): 148 vertices, not listed, extent 102.376,32.109 103.144,33.101
no net on Top Overlay "TOPOVERLAY729" (solid, pour order 0): 200 vertices, not listed, extent 103.31,32.109 103.957,33.089
no net on Top Overlay "TOPOVERLAY728" (solid, pour order 0): 312 vertices, not listed, extent 103.688,25.124 104.327,26.12
no net on Top Overlay "TOPOVERLAY727" (solid, pour order 0): 119 vertices, not listed, extent 101.995,25.14 102.853,26.116
no net on Top Overlay "TOPOVERLAY726" (solid, pour order 0): 200 vertices, not listed, extent 102.929,25.124 103.576,26.104
no net on Top Overlay "TOPOVERLAY725" (solid, pour order 0): 203 vertices, not listed, extent 103.635,34.166 104.278,35.162
no net on Top Overlay "TOPOVERLAY724" (solid, pour order 0): 119 vertices, not listed, extent 101.944,34.182 102.802,35.159
no net on Top Overlay "TOPOVERLAY723" (solid, pour order 0): 200 vertices, not listed, extent 102.878,34.166 103.525,35.146
no net on Top Overlay "TOPOVERLAY722" (solid, pour order 0): 103.676,22.244 103.676,23.105 103.354,23.105 103.354,23.221 104.129,23.221 104.129,23.105 103.806,23.105 103.806,22.244
no net on Top Overlay "TOPOVERLAY721" (solid, pour order 0): 48 vertices, not listed, extent 104.305,22.244 104.664,23.224
no net on Top Overlay "TOPOVERLAY720" (solid, pour order 0): 101.843,22.244 101.843,23.221 102.502,23.221 102.502,23.105 101.972,23.105 101.972,22.803 102.43,22.803 102.43,22.688 101.972,22.688 101.972,22.244
no net on Top Overlay "TOPOVERLAY719" (solid, pour order 0): 102.665,22.244 102.665,23.221 102.794,23.221 102.794,22.359 103.274,22.359 103.274,22.244
no net on Top Overlay "TOPOVERLAY718" (solid, pour order 0): 220 vertices, not listed, extent 102.492,49.558 103.137,50.555
no net on Top Overlay "TOPOVERLAY717" (solid, pour order 0): 148 vertices, not listed, extent 101.563,49.558 102.331,50.551
no net on Top Overlay "TOPOVERLAY716" (solid, pour order 0): 274 vertices, not listed, extent 100.039,69.421 100.902,70.431
no net on Top Overlay "TOPOVERLAY715" (solid, pour order 0): 200 vertices, not listed, extent 101.771,69.421 102.419,70.401
no net on Top Overlay "TOPOVERLAY714" (solid, pour order 0): 216 vertices, not listed, extent 100.998,69.437 101.642,70.418
no net on Top Overlay "TOPOVERLAY713" (solid, pour order 0): 274 vertices, not listed, extent 100.039,67.161 100.902,68.17
no net on Top Overlay "TOPOVERLAY712" (solid, pour order 0): 216 vertices, not listed, extent 100.998,67.177 101.642,68.157
no net on Top Overlay "TOPOVERLAY711" (solid, pour order 0): 102.156,67.177 102.156,67.41 101.732,67.41 101.732,67.52 102.178,68.153 102.276,68.153 102.276,67.52 102.407,67.52 102.407,67.41 102.276,67.41 102.276,67.177
no net on Top Overlay "TOPOVERLAY710" (solid, pour order 0): 312 vertices, not listed, extent 100.951,64.671 101.59,65.668
no net on Top Overlay "TOPOVERLAY709" (solid, pour order 0): 100 vertices, not listed, extent 100.014,64.688 100.822,65.664
no net on Top Overlay "TOPOVERLAY708" (solid, pour order 0): 274 vertices, not listed, extent 99.938,74.628 100.801,75.638
no net on Top Overlay "TOPOVERLAY707" (solid, pour order 0): 101.296,74.644 101.296,74.878 100.872,74.878 100.872,74.987 101.318,75.621 101.416,75.621 101.416,74.987 101.547,74.987 101.547,74.878 101.416,74.878 101.416,74.644
no net on Top Overlay "TOPOVERLAY706" (solid, pour order 0): 216 vertices, not listed, extent 101.654,74.644 102.299,75.625
no net on Top Overlay "TOPOVERLAY705" (solid, pour order 0): 220 vertices, not listed, extent 101.421,38.255 102.066,39.252
no net on Top Overlay "TOPOVERLAY704" (solid, pour order 0): 119 vertices, not listed, extent 99.734,38.272 100.593,39.248
no net on Top Overlay "TOPOVERLAY703" (solid, pour order 0): 200 vertices, not listed, extent 100.668,38.255 101.316,39.236
no net on Top Overlay "TOPOVERLAY702" (solid, pour order 0): 48 vertices, not listed, extent 99.929,59.176 100.288,60.156
no net on Top Overlay "TOPOVERLAY701" (solid, pour order 0): 99.122,59.176 99.122,60.152 99.252,60.152 99.252,59.291 99.732,59.291 99.732,59.176
no net on Top Overlay "TOPOVERLAY700" (solid, pour order 0): 200 vertices, not listed, extent 99.191,85.017 99.839,85.997
no net on Top Overlay "TOPOVERLAY699" (solid, pour order 0): 119 vertices, not listed, extent 97.499,85.033 98.357,86.009
no net on Top Overlay "TOPOVERLAY698" (solid, pour order 0): 216 vertices, not listed, extent 98.417,85.033 99.062,86.013
no net on Top Overlay "TOPOVERLAY697" (solid, pour order 0): 200 vertices, not listed, extent 99.138,25.149 99.785,26.129
no net on Top Overlay "TOPOVERLAY696" (solid, pour order 0): 119 vertices, not listed, extent 97.446,25.165 98.304,26.142
no net on Top Overlay "TOPOVERLAY695" (solid, pour order 0): 200 vertices, not listed, extent 98.379,25.149 99.027,26.129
